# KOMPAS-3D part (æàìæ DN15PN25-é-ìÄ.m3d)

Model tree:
1. Объединить компоненты:1  (labels: СЕНС DN15PN25-В-НО)

Referenced files in D:\Савин\!СЕНСОР\3D для заказчика\!Новый перечень\СЕНС\6. СЕНС-В-НО\DN15\: СЕНС DN15PN25-В-НО.a3d
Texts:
  СЕНС DN15PN25-В-НО
  ООО НПП Сенсор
